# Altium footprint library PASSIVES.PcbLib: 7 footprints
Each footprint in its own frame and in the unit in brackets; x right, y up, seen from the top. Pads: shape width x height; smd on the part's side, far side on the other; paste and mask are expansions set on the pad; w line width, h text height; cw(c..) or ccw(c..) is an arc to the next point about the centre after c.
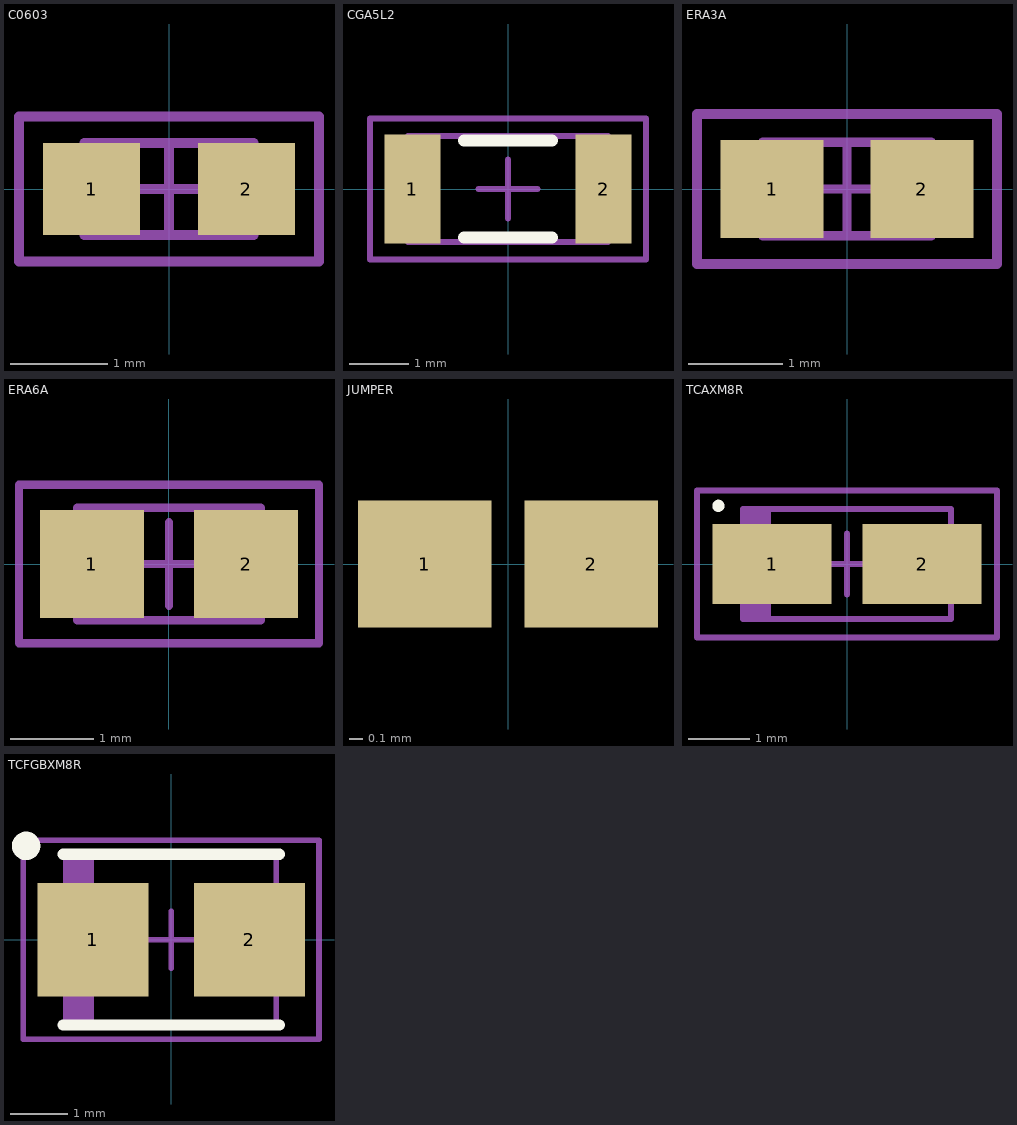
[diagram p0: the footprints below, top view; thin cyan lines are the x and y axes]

## C0603 [mm] "Kemet C0603 Ceramic Capacitor"
height 0.87
pads (2):
  rect 1x0.95 smd paste-254: 1(-0.8,0) 2(0.8,0)
Mechanical 13:
  lines w0.1: -0.875,-0.475 0.875,-0.475 0.875,0.475 -0.875,0.475 -0.875,-0.475
Mechanical 15:
  lines w0.05: -1.55,-0.75 1.55,-0.75 1.55,0.75 -1.55,0.75 -1.55,-0.75
  lines w0.1: -0.475,0 0.475,0 ; 0,-0.475 0,0.475
Mechanical 31:
  lines w0.102: -1.55,-0.75 -1.55,0.75 1.55,0.75 1.55,-0.75 -1.55,-0.75
  text ".Designator" at -1.05,0.125 h0.51
  text ".Comment" at -1.05,-0.625 h0.51
3D body: height 0.87, standoff 0, extent 0.525,-0.475 0.875,0.475
3D body: height 0.87, standoff 0, extent -0.875,-0.475 -0.525,0.475
3D body: height 0.87, standoff 0, extent -0.525,-0.475 0.525,0.475

## CGA5L2 [mm] "TDK CGA5L TDK Ceramic Capacitor"
height 1.6
pads (2):
  rect 0.95x1.85 smd: 1(-1.625,0) 2(1.625,0)
Top Overlay:
  lines w0.2: -0.75,-0.825 0.75,-0.825 ; -0.75,0.825 0.75,0.825
Mechanical 13:
  lines w0.1: -1.7,-0.9 1.7,-0.9 1.7,0.9 -1.7,0.9 -1.7,-0.9
Mechanical 15:
  lines w0.05: -2.35,-1.2 2.35,-1.2 2.35,1.2 -2.35,1.2 -2.35,-1.2
  lines w0.1: -0.5,0 0.5,0 ; 0,-0.5 0,0.5
Mechanical 31:
  lines w0.102: -2.35,-1.2 -2.35,1.2 2.35,1.2 2.35,-1.2 -2.35,-1.2
  text ".Comment" at -2,-0.85 h0.51
  text ".Designator" at -2.025,0.4 h0.51
3D body: height 1.6, standoff 0, extent 1.4,-0.9 1.7,0.9
3D body: height 1.6, standoff 0, extent -1.7,-0.9 -1.4,0.9
3D body: height 1.6, standoff 0, extent -1.4,-0.9 1.4,0.9

## ERA3A [mm] "ERA3A Panasonic Thin Film Resistor 0603"
height 0.55
pads (2):
  rect 1.1x1.05 smd: 1(-0.8,0) 2(0.8,0)
Mechanical 13:
  lines w0.1: -0.9,-0.5 0.9,-0.5 0.9,0.5 -0.9,0.5 -0.9,-0.5
Mechanical 15:
  lines w0.05: -1.6,-0.8 1.6,-0.8 1.6,0.8 -1.6,0.8 -1.6,-0.8
  lines w0.1: -0.5,0 0.5,0 ; 0,-0.5 0,0.5
Mechanical 31:
  lines w0.102: -1.6,-0.8 1.6,-0.8 1.6,0.8 -1.6,0.8 -1.6,-0.8
  text ".Comment" at -1.125,-0.65 h0.51
  text ".Designator" at -1.125,0.15 h0.51
3D body: height 0.55, standoff 0, extent 0.6,-0.5 0.9,0.5
3D body: height 0.55, standoff 0, extent -0.9,-0.5 -0.6,0.5
3D body: height 0.55, standoff 0, extent -0.6,-0.5 0.6,0.5

## ERA6A [mm] "ERA6A Panasonic Thin Film Resistor 0805"
height 0.6
pads (2):
  rect 1.25x1.3 smd: 1(-0.925,0) 2(0.925,0)
Mechanical 13:
  lines w0.1: -1.1,-0.675 1.1,-0.675 1.1,0.675 -1.1,0.675 -1.1,-0.675
Mechanical 15:
  lines w0.05: -1.8,-0.95 1.8,-0.95 1.8,0.95 -1.8,0.95 -1.8,-0.95
  lines w0.1: -0.5,0 0.5,0 ; 0,-0.5 0,0.5
Mechanical 31:
  lines w0.102: -1.8,-0.95 -1.8,0.95 1.8,0.95 1.8,-0.95 -1.8,-0.95
  text ".Designator" at -1.275,0.225 h0.51
  text ".Comment" at -1.3,-0.75 h0.51
3D body: height 0.6, standoff 0, extent 0.7,-0.675 1.1,0.675
3D body: height 0.6, standoff 0, extent -1.1,-0.675 -0.7,0.675
3D body: height 0.6, standoff 0, extent -0.7,-0.675 0.7,0.675

## JUMPER [mm] "Jumper"
pads (2):
  rect 1x0.95 smd mask+0.127: 1(-0.625,0) 2(0.625,0)

## TCAXM8R [mm] "TCA Tantalum Capacitor 1206 Rohm"
height 1.8
pads (2):
  rect 1.95x1.3 smd: 1(-1.225,0) 2(1.225,0)
Top Overlay:
  circle w0.1: c-2.1,0.95 r0.05
Mechanical 13:
  rectangle: -1.7,-0.9 -1.243,0.9
  lines w0.1: -1.7,-0.9 -1.7,0.9 1.7,0.9 1.7,-0.9 -1.7,-0.9
Mechanical 15:
  lines w0.05: -2.45,-1.2 -2.45,1.2 2.45,1.2 2.45,-1.2 -2.45,-1.2
  lines w0.1: -0.5,0 0.5,0 ; 0,-0.5 0,0.5
Mechanical 31:
  lines w0.102: -2.45,-1.2 -2.45,1.2 2.45,1.2 2.45,-1.2 -2.45,-1.2
  text ".Designator" at -1.725,0.225 h0.64
  text ".Comment" at -1.725,-0.775 h0.64
3D body: height 1.8, standoff 0, extent -1.7,-0.9 1.7,0.9

## TCFGBXM8R [mm] "Rohm TCFGB Series Tantalum Capacitor"
height 2.1
pads (2):
  rect 1.95x2 smd: 1(-1.375,0) 2(1.375,0)
Top Overlay:
  circle w0.25: c-2.55,1.65 r0.125
  lines w0.2: -1.9,-1.5 1.9,-1.5 ; -1.9,1.5 1.9,1.5
Mechanical 13:
  rectangle: -1.85,-1.5 -1.352,1.5
  lines w0.1: -1.85,-1.5 1.85,-1.5 1.85,1.5 -1.85,1.5 -1.85,-1.5
Mechanical 15:
  lines w0.05: -2.6,-1.75 2.6,-1.75 2.6,1.75 -2.6,1.75 -2.6,-1.75
  lines w0.1: -0.5,0 0.5,0 ; 0,-0.5 0,0.5
Mechanical 31:
  lines w0.102: -2.6,-1.75 -2.6,1.75 2.6,1.75 2.6,-1.75 -2.6,-1.75
  text ".Designator" at -1.8,0.6 h0.76
  text ".Comment" at -1.775,-1.125 h0.76
3D body: height 2.1, standoff 0, extent -1.85,-1.5 1.85,1.5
